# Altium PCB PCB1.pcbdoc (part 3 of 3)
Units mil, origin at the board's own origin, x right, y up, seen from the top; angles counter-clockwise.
Board outline 3256.12 x 1802.31 mil, 4 copper layers (Top Layer, Inner1, Inner2, Bottom Layer); 101 components, 70 nets, 295 pads, 151 vias.
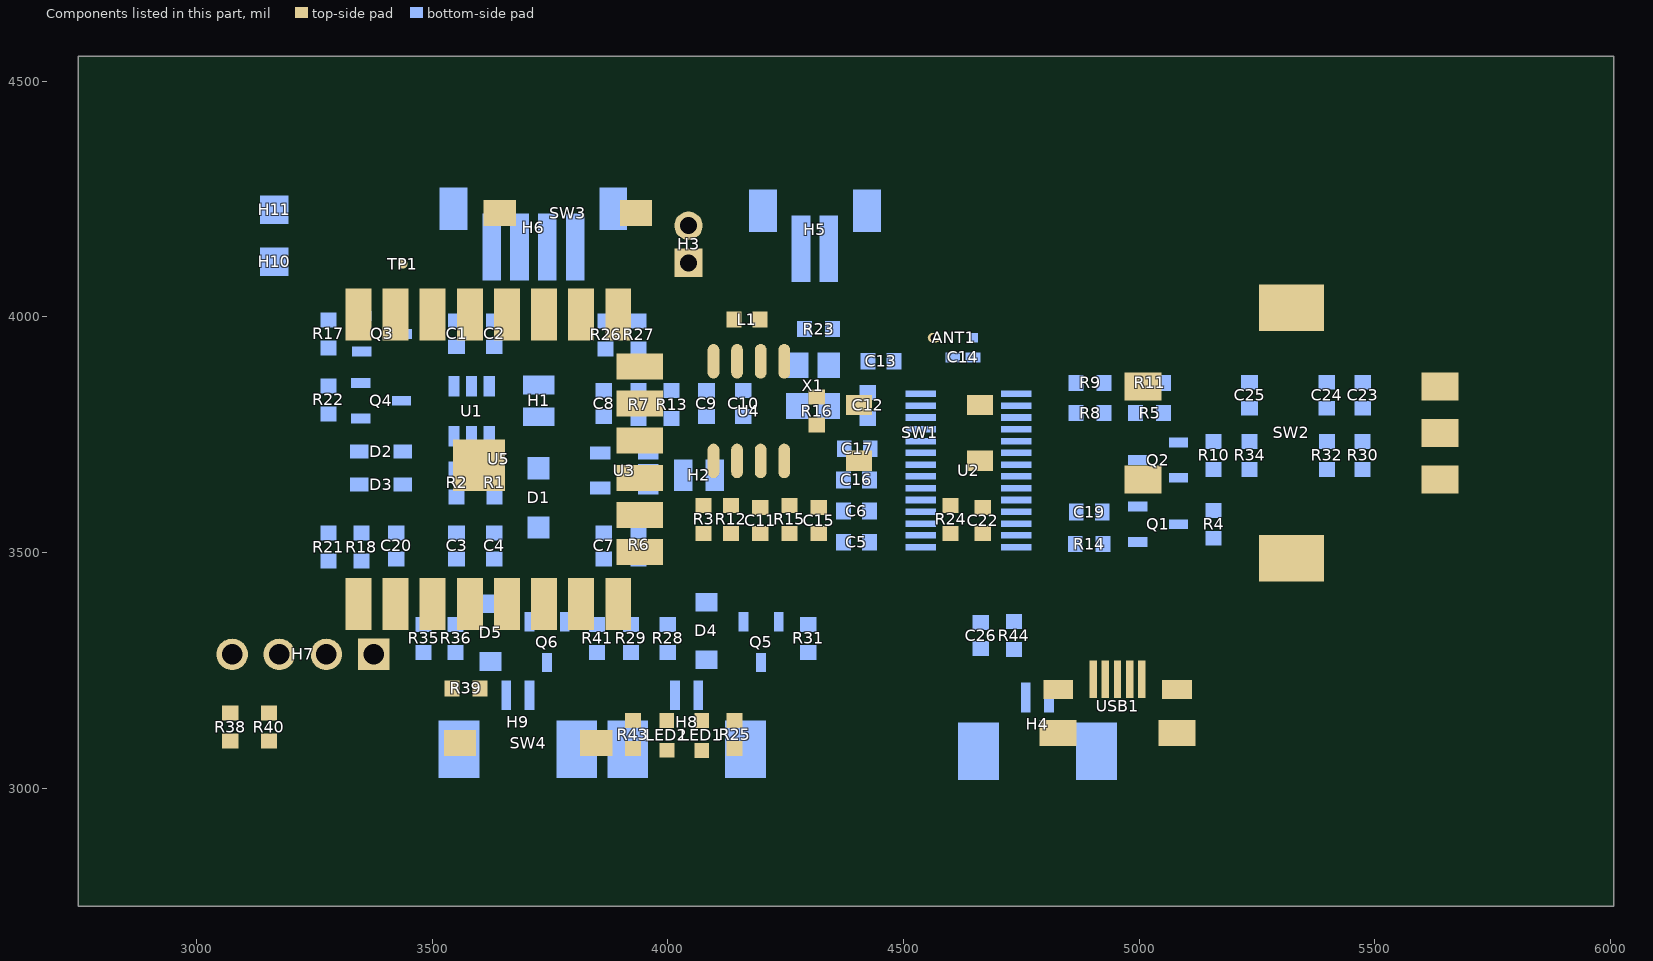
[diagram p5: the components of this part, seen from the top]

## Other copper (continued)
Bottom Layer:
  region net B+: 3260.01,4092 3372.01,4092 3372.01,3974 3260.01,3974
  region net $1N4815: 4638.01,3954 4658.01,3954 4658.01,3910 4638.01,3910
  region net VIN: 3414.01,3976 3414.01,3918 3456.01,3876 3520.01,3876 3530.01,3866 3530.01,3828 3534.01,3824 3594.01,3824 3598.01,3828 3598.01,3914 3604.01,3920 3653.92,3920 3659.96,3926.04 3659.96,3948.05 3654.01,3954 3464.01,3954 3460.01,3958 3460.01,3976 3458.01,3978 3416.01,3978
  region net VIN: 3598.01,3886 3610.01,3898 3678.01,3898 3690.01,3886 3690.01,3836 3692.01,3834 3758.01,3834 3762.01,3838 3762.01,3946 3754.01,3954 3596.01,3954 3596.01,3888
  region net $1N1680: 3608.01,3724 3608.01,3782 3616.01,3790 3668.01,3790 3690.01,3812 3760.01,3812 3764.01,3808 3764.01,3652 3760.01,3648 3678.01,3648 3674.01,3652 3674.01,3710 3660.01,3724
  region net +5V: 3528.09,3462.42 3528.09,3500.09 3534.01,3506 3696.01,3506 3700.01,3510 3700.01,3592 3696.01,3596 3614.01,3596 3610.01,3600 3610.01,3634 3614.01,3638 3820.82,3638 3835.31,3652.49 3879.51,3652.49 3884.01,3648 3884.01,3590 3882.01,3588 3820.01,3588 3814.01,3582 3814.01,3470 3806.01,3462 3528.51,3462
  region net VCC: 4079.8,3624.21 4080.01,3624 4079.8,3624
  region net VCC: 4082.01,3624 4080.01,3624 4082.01,3622
  region net VCC: 4062.01,3804 4062.01,3749.97 4074.01,3737.97 4074.01,3594 4080.01,3588 4190.01,3588 4196.01,3594 4196.01,3802 4190.01,3808 4066.01,3808
  region net $1N2005: 3936.01,3650 3938.01,3652 4008.01,3652 4012.01,3656 4012.01,3726 4014.01,3728 4052.01,3728 4054.01,3726 4054.01,3594 4048.01,3588 3944.01,3588 3936.01,3596
  region net VDDIO: 4569.44,3668.35 4449.66,3668.35 4444.01,3674 4412.01,3674 4410.01,3672 4410.01,3638 4414.14,3633.87 4442.53,3633.87 4460.01,3654 4570.01,3654.4 4570.01,3667.78
  region net +5V: 4412.01,3606 4412.01,3504 4444.01,3504 4444.01,3606
  region net VCC: 4196,3593.97 4196,3444 4190.01,3438 4070.01,3438 4064.01,3444 4064.01,3586 4074.01,3596 4195.57,3596 4196.01,3595.56 4196.01,3593.98
  region net +5V: 3803.9,3462 3803.9,3504 4040.01,3504 4044.01,3500 4044.01,3472 4034.01,3462
  region net VCC: 3896.72,3848.56 3896.72,3838.56 ccw(c3896.72,3819.81) 3881.72,3831.06 3881.72,3856.06 ccw(c3896.72,3867.31)
  region net $1N2017: 3869.01,3757.69 3859.01,3757.69 ccw(c3840.26,3757.69) 3851.51,3772.69 3876.51,3772.69 ccw(c3887.76,3757.69)
  region net $1N2017: 3896.72,3793.44 3896.72,3783.44 ccw(c3896.72,3764.69) 3881.72,3775.94 3881.72,3800.94 ccw(c3896.72,3812.19)
  region net VCC: 4059.04,3799.9 4063.58,3809.5 ccw(c4079.49,3830.71) 4079.49,3804.19 4064.34,3783.99 ccw(c4037.83,3783.99)
  region net +5V: 3557.51,3448.19 3542.51,3448.19 ccw(c3507.59,3448.19) 3534.29,3470.69 3568.76,3470.69 ccw(c3585.63,3448.19)
  region net +5V: 4435.5,3481.79 4420.5,3481.79 ccw(c4387.01,3481.79) 4411.81,3504.29 4443.31,3504.29 ccw(c4471.81,3481.79)
  region net +5V: 4444.01,3594 4444.01,3582 ccw(c4502.14,3573) 4443.31,3573 4443.31,3603 ccw(c4502.17,3603)
  region net $1N2789: 4394.29,3850 4394.29,3858 ccw(c4406.29,3883.4) 4406.29,3855.31 4406.29,3844 ccw(c4394.29,3835)
  region net $1N2789: 4454.45,3844.56 4454.45,3834.56 ccw(c4454.45,3820.02) 4441.72,3827.06 4441.72,3852.06 ccw(c4454.45,3859.1)
  region net $1N2785: 4444.44,3891.67 4440.75,3884.04 ccw(c4428.02,3867.07) 4428.02,3888.28 4440.19,3904.39 ccw(c4461.41,3904.39)
  region net $1N2785: 4396.7,3902 4396.7,3910 ccw(c4396.7,3925) 4408.7,3916 4408.7,3896 ccw(c4396.7,3887)
  region net $1N2965: 4450.62,3706.02 4445.51,3696.98 ccw(c4429.6,3675.77) 4429.6,3702.28 4445.31,3721.93 ccw(c4471.83,3721.93)
  region net $1N4810: 4613.51,3880.87 4598.51,3880.87 ccw(c4567.14,3880.87) 4588.99,3903.37 4620.1,3903.37 ccw(c4655.2,3880.87)
  region net DACL: 4946.01,3591 4946.01,3581 ccw(c4946.01,3572.21) 4937.31,3573.5 4937.31,3598.5 ccw(c4946.01,3599.79)
  region net PA0: 4845.39,3599.98 4850.5,3609.02 ccw(c4866.41,3630.23) 4866.41,3603.72 4850.7,3584.07 ccw(c4824.18,3584.07)
  region net EC11_A: 5478.95,3775.5 5468.95,3775.5 ccw(c5450.2,3775.5) 5461.45,3790.5 5486.45,3790.5 ccw(c5497.7,3775.5)
  region net EC11_B: 5403.06,3775.5 5393.06,3775.5 ccw(c5374.31,3775.5) 5385.56,3790.5 5410.56,3790.5 ccw(c5421.81,3775.5)
  region net EC11_D: 5239.06,3775.5 5229.06,3775.5 ccw(c5210.31,3775.5) 5221.56,3790.5 5246.56,3790.5 ccw(c5257.81,3775.5)
  region net POWER_ADC: 3433.51,3458 3418.51,3458 ccw(c3405.72,3458) 3407.26,3470.69 3441.72,3470.69 ccw(c3447.42,3458)
  region net POWER_ADC: 3383.79,3478.5 3383.79,3493.5 ccw(c3383.79,3526.98) 3406.29,3502.19 3406.29,3470.69 ccw(c3383.79,3442.18)
  region net $1N5780: 4751.98,3246.64 4766.98,3246.64 ccw(c4860.87,3246.64) 4769.72,3224.14 4749.25,3224.14 ccw(c4658.1,3246.64)
  region net SGND: 4838.92,3233.47 4830.78,3204.11 ccw(c4863.9,3170.99) 4818.94,3184.13 4818.94,3221.63 ccw(c4805.8,3266.59)
  region net $1N8684: 4097.35,3204.59 4097.35,3189.59 ccw(c4097.35,3161.46) 4074.85,3178.34 4074.85,3215.84 ccw(c4097.35,3232.71)
  region net $1N8688: 4007.9,3251.08 4022.9,3251.08 ccw(c4116.78,3251.08) 4025.63,3228.58 4005.16,3228.58 ccw(c3914.01,3251.08)
  region net $1N9109: 3699.12,3229.25 3714.12,3229.25 ccw(c3716.85,3234.51) 3716.85,3228.58 3696.38,3228.58 ccw(c3696.38,3234.51)
  region net $1N9106: 3649.9,3235.59 3664.9,3235.59 ccw(c3675.24,3235.59) 3667.63,3228.58 3647.16,3228.58 ccw(c3639.55,3235.59)
  region net $1N10424: 3430.37,3743.76 3440.37,3743.76 ccw(c3459.12,3743.76) 3447.87,3728.76 3422.87,3728.76 ccw(c3411.62,3743.76)
  region net EC11_D: 3353.34,3676.74 3338.34,3676.74 ccw(c3310.22,3676.74) 3327.09,3699.24 3364.59,3699.24 ccw(c3381.47,3676.74)
  region net EC11_D: 3378.11,3721.5 3378.11,3706.5 ccw(c3378.11,3691.97) 3365.53,3699.24 3365.53,3728.76 ccw(c3378.11,3736.03)
  region net POWER_SW: 3445.67,3610.16 3430.67,3610.16 ccw(c3408.88,3610.16) 3419.42,3629.24 3456.92,3629.24 ccw(c3467.46,3610.16)
  region net EC11_D: 3338.34,3681.26 3353.34,3681.26 ccw(c3381.47,3681.26) 3364.59,3658.76 3327.09,3658.76 ccw(c3310.22,3681.26)
  region net $1N9109: 3655.58,3370.05 3641.04,3363.38 ccw(c3617.17,3331.56) 3617.17,3371.34 3647.63,3393.91 ccw(c3687.4,3393.91)
  region net $1N9106: 3577.88,3280.84 3577.88,3295.84 ccw(c3600.38,3327.53) 3600.38,3288.66 3600.38,3269.59 ccw(c3577.88,3252.72)
  region net $1N9106: 3655.58,3248.01 3641.04,3241.34 ccw(c3617.17,3209.52) 3617.17,3249.3 3647.63,3271.87 ccw(c3687.4,3271.87)
  region net $1N8684: 4083.51,3364 4068.51,3364 ccw(c4057.1,3364) 4058.38,3375.34 4094.76,3375.34 ccw(c4094.84,3364)
  region net $1N8688: 4035.88,3280.84 4035.88,3295.84 ccw(c4058.38,3373.98) 4058.38,3292.66 4058.38,3269.59 ccw(c4035.88,3252.72)
  region net $1N2005: 4008.64,3633.02 4004.96,3643.49 ccw(c3982.89,3665.57) 4012.86,3656.82 4012.86,3631.82 ccw(c4010.41,3631.25)
  region net VCC: 3406.82,3325.42 3417.43,3314.81 ccw(c3449.24,3290.95) 3409.47,3290.95 3382.95,3317.46 ccw(c3382.95,3357.24)
  region net $1N5279: 5007.94,3540.96 5026.24,3545.12 ccw(c5066.03,3505.33) 5017.07,3533.07 4994.62,3533.07 ccw(c4985.86,3563.04)
  region net PA2: 4967.06,3619.92 4985.35,3615.76 ccw(c5007.43,3637.84) 4998.67,3607.87 4976.22,3607.87 ccw(c4927.27,3580.13)
  region net TXD: 5097.05,3575.78 5109.09,3573.68 ccw(c5130.3,3557.77) 5103.79,3557.77 5081.14,3570.47 ccw(c5081.14,3596.99)
  region net $1N5314: 5047.94,3727 5047.94,3737 ccw(c5047.94,3756.81) 5062.94,3743.87 5062.94,3722.93 ccw(c5047.94,3697.34)
  region net RXD: 5078.37,3684 5088.37,3684 ccw(c5106.97,3684) 5095.87,3669.07 5070.87,3669.07 ccw(c5059.76,3684)
  region net PA3: 4991.65,3721.47 5001.65,3721.47 ccw(c5020.4,3721.47) 5009.15,3706.47 4984.15,3706.47 ccw(c4972.9,3721.47)
  region net PA3: 4961.22,3681.5 4961.22,3691.5 ccw(c4961.22,3710.25) 4976.22,3699 4976.22,3685.53 ccw(c4976.22,3655.58)
  region net $1N8729: 4179.03,3345.54 4178.38,3324.98 ccw(c4154.51,3293.16) 4154.51,3332.94 4171.08,3369.4 ccw(c4210.85,3369.4)
  region net $1N8684: 4180.23,3238.26 4179.58,3258.82 ccw(c4147.76,3282.68) 4187.53,3282.68 4204.1,3246.22 ccw(c4204.1,3206.44)
  region net $1N9116: 3699.11,3382.6 3714.11,3382.6 ccw(c3728.67,3382.6) 3717.08,3373.78 3696.13,3373.78 ccw(c3684.54,3382.6)
  region net $1N9109: 3726.23,3238.26 3725.58,3258.82 ccw(c3693.76,3282.68) 3733.53,3282.68 3750.1,3246.22 ccw(c3750.1,3206.44)
  region net $1N9109: 3711.03,3259.14 3711.03,3274.14 ccw(c3711.03,3302.26) 3733.53,3285.39 3733.53,3247.89 ccw(c3711.03,3231.01)
  region net $1N10424: 3376.83,3921.62 3373.49,3910.82 ccw(c3357.58,3889.61) 3357.58,3916.13 3371.07,3937.07 ccw(c3394.65,3937.07)
  region net $1N10424: 3315.22,3921.6 3315.22,3931.6 ccw(c3315.22,3954.89) 3330.22,3937.07 3330.22,3916.13 ccw(c3315.22,3898.31)
  region net $1N10478: 3319.27,3807.33 3337.77,3802.96 ccw(c3359.85,3825.04) 3351.09,3795.07 3328.22,3795.07 ccw(c3284.34,3772.41)
  region net $1N10424: 3427.01,3847.47 3437.01,3847.47 ccw(c3455.76,3847.47) 3444.51,3832.47 3419.51,3832.47 ccw(c3408.26,3847.47)
  region net $1N10424: 3440.37,3796.53 3430.37,3796.53 ccw(c3411.62,3796.53) 3422.87,3811.53 3447.87,3811.53 ccw(c3459.12,3796.53)
  region net $1N1955: 3915.7,3555.24 3918.05,3567.03 ccw(c3933.96,3588.24) 3933.96,3561.73 3921,3539.33 ccw(c3894.48,3539.33)
  region net +5V: 3929.51,3448.15 3914.51,3448.15 ccw(c3878.77,3470.65) 3921,3470.65 3940.76,3470.65 ccw(c3957.63,3448.15)
  region net VCC: 3906,3838.56 3906,3848.56 ccw(c3906,3867.31) 3921,3856.06 3921,3831.06 ccw(c3906,3819.81)
  region net VCC: 3955.58,3864.65 3960.32,3855.24 ccw(c3981.53,3839.33) 3955.01,3839.33 3939.67,3859.35 ccw(c3939.67,3885.86)
  region net $1N2017: 3906,3783.44 3906,3793.44 ccw(c3906,3813.82) 3921,3800.03 3921,3775.94 ccw(c3906,3764.69)
  region net $1N2017: 3966.89,3809.37 3962.91,3791.25 ccw(c3984.99,3769.17) 3955.01,3777.93 3955.01,3800.03 ccw(c3921.76,3854.5)
  region net $1N2017: 3993.95,3822.29 3985.75,3828.23 ccw(c3964.53,3844.14) 3991.05,3844.14 4009.86,3827.59 ccw(c4009.86,3801.08)
  region net $1N1696: 3541.61,3708.54 3551.61,3708.54 ccw(c3570.36,3708.54) 3559.11,3693.54 3535,3693.54 ccw(c3521.28,3708.54)
  region net $1N1696: 3584.01,3682.66 3584.01,3672.66 ccw(c3584.01,3653.91) 3569.01,3665.16 3569.01,3690.16 ccw(c3584.01,3701.41)
  region net $1N1696: 3600,3672.66 3600,3682.66 ccw(c3600,3701.41) 3615,3690.16 3615,3665.16 ccw(c3600,3653.91)
  region net USB_DP: 4871.35,3770.34 4861.35,3770.34 ccw(c4852.61,3770.34) 4853.85,3778.99 4878.85,3778.99 ccw(c4880.09,3770.34)
  region net USB_DM: 4851.11,3837.69 4845.17,3845.89 ccw(c4823.95,3861.8) 4850.47,3861.8 4867.02,3842.99 ccw(c4867.02,3816.48)
  region net $1N5279: 5144.24,3655.16 5135.69,3660.76 ccw(c5114.48,3676.67) 5141,3676.67 5160.15,3660.46 ccw(c5160.15,3633.95)
  region net VDDIO: 5135.69,3750.9 5143.9,3756.84 ccw(c5159.81,3778.05) 5159.81,3751.54 5141,3734.99 ccw(c5114.48,3734.99)
  region net $1N5314: 5013.52,3845.89 5007.59,3837.69 ccw(c4991.68,3816.48) 4991.68,3842.99 5008.22,3861.8 ccw(c5034.74,3861.8)
  region net VDDIO: 5027.84,3873.22 5037.31,3884.96 ccw(c5061.17,3916.78) 5061.17,3877.01 5035.79,3849.36 ccw(c4996.02,3849.36)
  region net VDDIO: 5056.67,3827.99 5046.67,3827.99 ccw(c5027.92,3827.99) 5039.17,3842.99 5064.17,3842.99 ccw(c5075.42,3827.99)
  region net TXD: 5126,3584.66 5126,3594.66 ccw(c5126,3613.41) 5141,3602.16 5141,3577.16 ccw(c5126,3565.91)
  region net +5V: 5184.2,3547.27 5180.88,3529.81 ccw(c5198,3514.46) 5175.01,3514.46 5175.01,3546.22 ccw(c5178.95,3552.53)
  region net PA3: 5001.65,3763.99 4991.65,3763.99 ccw(c4972.9,3763.99) 4984.15,3778.99 5008.22,3778.99 ccw(c5022.04,3763.99)
  region net VDDIO: 5082.54,3801 5082.54,3791 ccw(c5082.54,3772.25) 5067.54,3783.5 5067.54,3808.5 ccw(c5082.54,3819.75)
  region net VDDIO: 5046.67,3828.01 5056.67,3828.01 ccw(c5075.42,3828.01) 5064.17,3813.01 5039.17,3813.01 ccw(c5027.92,3828.01)
  region net SGND: 4871.85,3478.49 4856.85,3478.49 ccw(c4822.44,3478.49) 4848.47,3500.99 4880.22,3500.99 ccw(c4906.26,3478.49)
  region net SGND: 4841.58,3531.58 4850.44,3541.1 ccw(c4870.32,3570.5) 4870.32,3535.01 4848.47,3510.89 ccw(c4814,3510.89)
  region net +5V: 4267.04,3986.7 4277.65,3997.3 ccw(c4299.85,4033.32) 4299.85,3991.01 4274.47,3963.36 ccw(c4234.09,3963.36)
  region net MUSIC_SW: 4381.96,3981.5 4381.96,3966.5 ccw(c4381.96,3947.56) 4365.54,3956.99 4365.54,3991.01 ccw(c4381.96,4000.44)
  region net MUSIC_SW: 4342.17,4000.34 4357.17,4000.34 ccw(c4366.55,4000.34) 4365.54,3991.01 4333.79,3991.01 ccw(c4332.78,4000.34)
  region net VCC: 3992.51,3384 4007.51,3384 ccw(c4034.28,3384) 4017.01,3363.54 3983,3363.54 ccw(c3965.73,3384)
  region net $1N8688: 4022.9,3249.96 4007.9,3249.96 ccw(c3979.77,3249.96) 3996.65,3272.46 4017.01,3272.46 ccw(c4062.99,3272.46)
  region net $1N8688: 4039.51,3295.84 4039.51,3280.84 ccw(c4039.51,3246.43) 4017.01,3272.46 4017.01,3304.22 ccw(c4039.51,3330.25)
  region net $1N8688: 3960.5,3280.84 3960.5,3295.84 ccw(c3960.5,3330.25) 3983,3304.22 3983,3272.46 ccw(c3960.5,3246.43)
  region net +5V: 3914.51,3386.04 3929.51,3386.04 ccw(c3960.88,3386.04) 3939.01,3363.54 3905,3363.54 ccw(c3883.13,3386.04)
  region net $1N8688: 3961.51,3295.84 3961.51,3280.84 ccw(c3961.51,3246.43) 3939.01,3272.46 3939.01,3304.22 ccw(c3961.51,3330.25)
  region net $1N8729: 4273.04,3302.7 4284.78,3312.17 ccw(c4308.65,3343.99) 4308.65,3304.22 4281,3278.83 ccw(c4241.22,3278.83)
  region net LED_PWM: 4330.01,3352.66 4330.01,3342.66 ccw(c4330.01,3323.91) 4315.01,3335.16 4315.01,3360.16 ccw(c4330.01,3371.41)
  region net VCC: 3442.5,3340.16 3442.5,3355.16 ccw(c3442.5,3389.57) 3465,3363.54 3465,3331.78 ccw(c3442.5,3305.75)
  region net $1N9106: 3521.51,3295.84 3521.51,3280.84 ccw(c3521.51,3246.43) 3499.01,3272.46 3499.01,3304.22 ccw(c3521.51,3330.25)
  region net +5V: 3542.51,3386.04 3557.51,3386.04 ccw(c3588.88,3386.04) 3567.01,3363.54 3533,3363.54 ccw(c3511.13,3386.04)
  region net $1N9106: 3589.51,3295.84 3589.51,3280.84 ccw(c3589.51,3246.43) 3567.01,3272.46 3567.01,3304.22 ccw(c3589.51,3330.25)
  region net $1N9106: 3510.5,3280.84 3510.5,3295.84 ccw(c3510.5,3330.25) 3533,3304.22 3533,3272.46 ccw(c3510.5,3246.43)
  region net $1N9116: 3842.51,3370 3857.51,3370 ccw(c3867.01,3373.76) 3867.01,3363.54 3833,3363.54 ccw(c3833,3373.76)
  region net MOTOR_PWM: 3857.51,3260 3842.51,3260 ccw(c3829.58,3260) 3833,3272.46 3867.01,3272.46 ccw(c3870.43,3260)
  region net +5V: 5442,3671.34 5442,3681.34 ccw(c5442,3700.09) 5457,3688.84 5457,3663.84 ccw(c5442,3652.59)
  region net EC11_A: 5468.95,3766.54 5478.95,3766.54 ccw(c5497.7,3766.54) 5486.45,3751.54 5461.45,3751.54 ccw(c5450.2,3766.54)
  region net +5V: 5380.24,3655.16 5375.69,3664.76 ccw(c5354.48,3680.67) 5381,3680.67 5396.15,3660.46 ccw(c5396.15,3633.95)
  region net +5V: 5430.01,3681.34 5430.01,3671.34 ccw(c5430.01,3652.59) 5415.01,3663.84 5415.01,3688.84 ccw(c5430.01,3700.09)
  region net EC11_B: 5393.06,3766.54 5403.06,3766.54 ccw(c5421.81,3766.54) 5410.56,3751.54 5385.56,3751.54 ccw(c5374.31,3766.54)
  region net +5V: 5239.01,3645.46 5229.01,3645.46 ccw(c5210.26,3645.46) 5221.51,3660.46 5246.51,3660.46 ccw(c5257.76,3645.46)
  region net EC11_D: 5219.9,3714.48 5211.69,3720.42 ccw(c5190.48,3736.33) 5217,3736.33 5235.81,3719.78 ccw(c5235.81,3693.27)
  region net EC11_D: 5229.06,3766.54 5239.06,3766.54 ccw(c5257.81,3766.54) 5246.56,3751.54 5221.56,3751.54 ccw(c5210.31,3766.54)
  region net $1N10424: 3312.01,3931.6 3312.01,3921.6 ccw(c3312.01,3884.15) 3297.01,3918.46 3297.01,3939.1 ccw(c3312.01,3950.35)
  region net POWER_IO: 3304.97,3779.98 3293.23,3770.51 ccw(c3269.36,3738.69) 3269.36,3778.46 3297.01,3803.85 ccw(c3336.79,3803.85)
  region net $1N10478: 3302.32,3838.42 3294.11,3832.48 ccw(c3278.2,3811.27) 3278.2,3837.78 3297.01,3854.33 ccw(c3323.53,3854.33)
  region net VIN: 3356.17,3565.23 3375.32,3570.25 ccw(c3400.95,3544.62) 3367.01,3557.34 3342.85,3557.34 ccw(c3334.09,3587.31)
  region net POWER_ADC: 3310.5,3474.65 3310.5,3489.65 ccw(c3310.5,3524.06) 3333,3498.02 3333,3466.27 ccw(c3310.5,3440.24)
  region net POWER_ADC: 3389.51,3493.5 3389.51,3478.5 ccw(c3389.51,3450.38) 3367.01,3467.25 3367.01,3498.02 ccw(c3389.51,3551.74)
  region net POWER_ADC: 3319.51,3489.65 3319.51,3474.65 ccw(c3319.51,3440.24) 3297.01,3466.27 3297.01,3498.02 ccw(c3319.51,3524.06)
  region net POWER_LED: 3854.73,3908.32 3842.99,3917.79 ccw(c3811.17,3941.65) 3850.95,3941.65 3878.6,3916.27 ccw(c3878.6,3876.5)
  region net $1N10993: 3844.01,3985 3844.01,3995 ccw(c3843.42,4002.5) 3850.95,4002.5 3850.95,3977.5 ccw(c3843.42,3977.5)
  region net SPK_LED: 3924.78,3908.32 3913.04,3917.79 ccw(c3881.22,3941.65) 3921,3941.65 3948.65,3916.27 ccw(c3948.65,3876.5)
  region net $1N10998: 3933.01,4013.96 3943.01,4013.96 ccw(c3950.51,4014.9) 3950.51,4007.34 3925.51,4007.34 ccw(c3925.51,4014.9)
  region net $1N1696: 3551.61,3710.2 3541.61,3710.2 ccw(c3521.68,3710.2) 3534.79,3725.2 3558.42,3725.2 ccw(c3571.53,3710.2)
  region net VIN: 3522.8,3822.28 3526.9,3840.52 ccw(c3504.82,3862.6) 3534.79,3853.84 3534.79,3831.5 ccw(c3564.09,3780.99)
  region net $1N2017: 3859.01,3740.14 3869.01,3740.14 ccw(c3887.76,3740.14) 3876.51,3725.14 3851.51,3725.14 ccw(c3840.26,3740.14)
  region net $1N2005: 3995.6,3641.56 3995.6,3631.56 ccw(c3995.6,3612.81) 3980.6,3624.06 3980.6,3649.06 ccw(c3995.6,3660.31)
  region net $1N1955: 3927.45,3706.44 3927.45,3716.44 ccw(c3927.45,3726.66) 3937.3,3723.94 3937.3,3698.94 ccw(c3927.45,3696.22)
  region net DACR: 4541.05,3492.97 4531.05,3492.97 ccw(c4518.43,3492.97) 4523.55,3504.5 4548.55,3504.5 ccw(c4553.66,3492.97)
  region net MOTOR_PWM: 4504.51,3531.5 4504.51,3541.5 ccw(c4449.73,3543.5) 4504.54,3543.5 4504.54,3529.5 ccw(c4449.73,3529.5)
  region net LED_PWM: 4491.51,3556.5 4491.51,3566.5 ccw(c4491.51,3609.99) 4504.54,3568.5 4504.54,3554.5 ccw(c4491.51,3513.01)
  region net +5V: 4492.19,3630.19 4492.19,3642.19 ccw(c4492.19,3701.02) 4504.54,3643.5 4504.54,3629.5 ccw(c4492.19,3519.15)
  region net $1N2965: 4489.54,3681.5 4489.54,3691.5 ccw(c4489.54,3748.75) 4504.54,3693.5 4504.54,3679.5 ccw(c4489.54,3624.25)
  region net $1N2789: 4489.54,3806.5 4489.54,3816.5 ccw(c4489.54,3873.75) 4504.54,3818.5 4504.54,3804.5 ccw(c4489.54,3749.25)
  region net $1N2785: 4493.95,3832.5 4493.95,3840.5 ccw(c4493.95,3860.71) 4504.54,3843.5 4504.54,3829.5 ccw(c4493.95,3812.29)
  region net KEY_IO: 4691.9,3831.5 4691.9,3841.5 ccw(c4691.9,3898.75) 4706.9,3843.5 4706.9,3829.5 ccw(c4691.9,3774.25)
  region net EC11_B: 4784.46,3816.5 4784.46,3806.5 ccw(c4784.46,3763.33) 4771.47,3804.5 4771.47,3818.5 ccw(c4784.46,3859.67)
  region net EC11_A: 4786.47,3793.57 4786.47,3783.57 ccw(c4786.47,3753.93) 4771.47,3779.5 4771.47,3793.5 ccw(c4771.47,5295.51)
  region net USB_DM: 4786.47,3766.5 4786.47,3756.5 ccw(c4786.47,3699.25) 4771.47,3754.5 4771.47,3768.5 ccw(c4786.47,3823.75)
  region net USB_DP: 4786.47,3741.5 4786.47,3731.5 ccw(c4786.47,3674.25) 4771.47,3729.5 4771.47,3743.5 ccw(c4786.47,3798.75)
  region net PA3: 4786.47,3691.5 4786.47,3681.5 ccw(c4786.47,3624.25) 4771.47,3679.5 4771.47,3693.5 ccw(c4786.47,3748.75)
  region net PA2: 4786.47,3666.5 4786.47,3656.5 ccw(c4786.47,3599.25) 4771.47,3654.5 4771.47,3668.5 ccw(c4786.47,3723.75)
  region net PA1: 4691.9,3631.5 4691.9,3641.5 ccw(c4691.9,3698.75) 4706.9,3643.5 4706.9,3629.5 ccw(c4691.9,3574.25)
  region net PA0: 4786.47,3616.5 4786.47,3606.5 ccw(c4786.47,3549.25) 4771.47,3604.5 4771.47,3618.5 ccw(c4786.47,3673.75)
  region net PC7: 4698.51,3581.5 4698.51,3591.5 ccw(c4698.51,3610.13) 4706.9,3593.5 4706.9,3579.5 ccw(c4698.51,3562.87)
  region net SGND: 4790.97,3543 4790.97,3530 ccw(c4790.97,3149.5) 4771.47,3529.5 4771.47,3543.5 ccw(c4790.97,3923.5)
  region net DACL: 4786.47,3516.5 4786.47,3506.5 ccw(c4786.47,3449.25) 4771.47,3504.5 4771.47,3518.5 ccw(c4786.47,3573.75)
  region net SPK+: 4054.01,4054.63 4034.01,4054.63 ccw(c3996.51,4054.63) 4019.01,4084.63 4069.01,4084.63 ccw(c4091.51,4054.63)
  region net B+: 3564.19,4057.86 3575.17,4125.4 ccw(c3486.85,4213.72) 3606.74,4178.69 3606.74,4078.69 ccw(c3615.86,4006.19)
  region net $1N10993: 3774.5,4066.58 3757.32,4069.61 ccw(c3735.24,4047.54) 3744,4077.51 3764.22,4077.51 ccw(c3948.69,4240.77)
  region net $1N10998: 3831.17,4127.87 3836.6,4108.3 ccw(c3814.52,4086.22) 3823.28,4116.19 3823.28,4141.19 ccw(c3853.25,4149.95)
  region net $1N2789: 4294.69,3842.49 4302.41,3838.9 ccw(c4319.38,3826.17) 4298.16,3826.17 4281.96,3838.25 ccw(c4281.96,3859.46)
  region net $1N2785: 4377.09,3910 4377.09,3902 ccw(c4377.09,3887) 4365.09,3896 4365.09,3916 ccw(c4377.09,3925)
  region net PA1: 4659.01,3382.31 4669.01,3382.31 ccw(c4687.76,3382.31) 4676.51,3367.31 4651.51,3367.31 ccw(c4640.26,3382.31)
  region net $1N5780: 4704.22,3301.84 4704.22,3286.84 ccw(c4704.22,3242.59) 4681.72,3280.69 4681.72,3312.19 ccw(c4704.22,3331.48)
  region net $1N5780: 4694.5,3286.84 4694.5,3301.84 ccw(c4694.5,3336.25) 4717,3310.22 4717,3278.46 ccw(c4694.5,3252.43)
  region net $1N5780: 4758.97,3279.98 4747.23,3270.51 ccw(c4723.36,3238.69) 4723.36,3278.46 4751.01,3303.85 ccw(c4790.79,3303.85)
  region net PC7: 4711.69,3368.9 4719.9,3374.84 ccw(c4735.81,3396.05) 4735.81,3369.54 4717,3352.99 ccw(c4690.48,3352.99)
  region net B+: 3249.01,4125 3249.01,4085 ccw(c3195.01,3357) 3195.01,4087 3195.01,4147 ccw(c3249.01,4202.27)
  region net MUSIC_SW: 4365.62,3966.5 4365.62,3981.5 4367.99,3981.42 4370.13,3981.42 4371.14,3981.56 4372.12,3981.84 4373.08,3982.31 4374.02,3983.01 4374.02,3964.99 4373.08,3965.69 4372.12,3966.16 4371.14,3966.44 4370.13,3966.58 4367.99,3966.58
  region net MOTOR_PWM: 3842.51,3276.35 3857.51,3276.35 3857.43,3273.97 3857.43,3271.83 3857.56,3270.82 3857.84,3269.84 3858.31,3268.89 3859.01,3267.94 3841,3267.94 3841.7,3268.89 3842.17,3269.84 3842.45,3270.82 3842.58,3271.83 3842.58,3273.97
  region net MOTOR_PWM: 4480.03,3391.1 4487.1,3384.02 4486.36,3383.16 4485.74,3382.17 4484.81,3379.97 4484.26,3377.59 4483.99,3375.25 4471.25,3387.98 4473.6,3388.25 4475.97,3388.81 4478.18,3389.73 4479.16,3390.35
  region net +5V: 4420.5,3486.32 4435.5,3486.32 4435.42,3483.95 4435.42,3481.81 4435.55,3480.8 4435.83,3479.82 4436.3,3478.86 4437,3477.92 4418.99,3477.92 4419.69,3478.86 4420.16,3479.82 4420.44,3480.8 4420.58,3481.81 4420.57,3483.95
  region net +5V: 5229.01,3660.35 5239.01,3660.35 5239.1,3659.21 5239.35,3658.08 5240.26,3655.86 5241.54,3653.79 5243.01,3651.94 5225,3651.94 5226.47,3653.79 5227.75,3655.86 5228.66,3658.08 5228.92,3659.21
  region net +5V: 5247.54,3637.54 5240.47,3630.46 5239.67,3631.14 5238.86,3631.58 5238.04,3631.85 5237.19,3631.97 5233.25,3632.02 5245.99,3644.75 5246.03,3640.81 5246.16,3639.96 5246.42,3639.14 5246.87,3638.34
  region net DACL: 4811.82,3506.5 4811.82,3516.5 4812.96,3516.59 4814.1,3516.84 4816.31,3517.75 4818.38,3519.03 4820.23,3520.51 4820.23,3502.49 4818.38,3503.97 4816.31,3505.25 4814.1,3506.16 4812.96,3506.41
  region net DACL: 4929.66,3581 4929.66,3591 4930.8,3591.09 4931.93,3591.34 4934.14,3592.25 4936.22,3593.53 4938.06,3595.01 4938.06,3576.99 4936.22,3578.47 4934.14,3579.75 4931.93,3580.66 4930.8,3580.91
  region net MUSIC_SW: 4627.01,3719.65 4613.01,3719.65 4612.98,3721.94 4612.76,3724.14 4612.17,3726.21 4611.67,3727.16 4611,3728.06 4629.01,3728.06 4628.34,3727.16 4627.84,3726.21 4627.25,3724.14 4627.03,3721.94
  region net VDDIO: 5069.66,3791 5069.66,3801 5070.8,3801.09 5071.93,3801.34 5074.14,3802.25 5076.22,3803.53 5078.06,3805.01 5078.06,3786.99 5076.22,3788.47 5074.14,3789.75 5071.93,3790.66 5070.8,3790.91
  region net VDDIO: 5101.2,3799.54 5102.72,3783.88 5100.56,3785.95 5099.47,3786.83 5098.38,3787.5 5097.29,3787.92 5096.18,3788.02 5095.05,3787.72 5093.91,3786.96 5094.2,3804.78 5096.21,3803.13 5097.74,3802.2 5099.25,3801.24
  region net +5V: 5179.72,3528.64 5172.64,3535.71 5173.39,3536.58 5174.01,3537.56 5174.93,3539.77 5175.49,3542.14 5175.76,3544.49 5188.49,3531.75 5186.15,3531.49 5183.77,3530.93 5181.57,3530 5180.58,3529.38
  region net KEY_IO: 4657.01,3750.35 4667.01,3750.35 4667.1,3749.21 4667.35,3748.08 4668.26,3745.86 4669.54,3743.79 4671.01,3741.94 4653,3741.94 4654.47,3743.79 4655.75,3745.86 4656.66,3748.08 4656.92,3749.21
  region net USB_DM: 4775.48,3756.5 4775.48,3766.5 4776.62,3766.59 4777.75,3766.84 4779.97,3767.75 4782.04,3769.03 4783.89,3770.51 4783.89,3752.49 4782.04,3753.97 4779.97,3755.25 4777.75,3756.16 4776.62,3756.41
  region net USB_DM: 4808.18,3766.5 4808.18,3756.5 4807.04,3756.41 4805.91,3756.16 4803.69,3755.25 4801.62,3753.97 4799.77,3752.49 4799.77,3770.51 4801.62,3769.03 4803.69,3767.75 4805.91,3766.84 4807.04,3766.59
  region net USB_DP: 4816.16,3731.5 4816.16,3741.5 4817.3,3741.59 4818.43,3741.84 4820.64,3742.75 4822.72,3744.03 4824.56,3745.51 4824.56,3727.49 4822.72,3728.97 4820.64,3730.25 4818.43,3731.16 4817.3,3731.41
  region net USB_DP: 4840.53,3751.6 4847.6,3744.52 4846.86,3743.66 4846.24,3742.67 4845.31,3740.47 4844.76,3738.09 4844.49,3735.75 4831.75,3748.48 4834.1,3748.75 4836.47,3749.31 4838.68,3750.23 4839.66,3750.85
  region net TXD: 5110.32,3574.9 5103.25,3581.98 5103.99,3582.84 5104.61,3583.83 5105.54,3586.03 5106.1,3588.41 5106.36,3590.75 5119.1,3578.02 5116.75,3577.75 5114.38,3577.19 5112.17,3576.27 5111.19,3575.65
  region net TXD: 5134.95,3594.66 5134.44,3584.66 5133.3,3584.57 5132.17,3584.33 5129.97,3583.45 5127.9,3582.2 5126.03,3580.77 5126.54,3598.78 5128.36,3597.27 5130.44,3595.95 5132.67,3595.01 5133.81,3594.75
  region net RXD: 5088.37,3666.41 5078.37,3666.41 5078.28,3667.54 5078.02,3668.68 5077.11,3670.89 5075.83,3672.97 5074.36,3674.81 5092.37,3674.81 5090.9,3672.97 5089.62,3670.89 5088.71,3668.68 5088.46,3667.54
  region net EC11_B: 5393.06,3786.71 5403.06,3785.78 5403.14,3784.64 5403.38,3783.52 5404.24,3781.33 5405.45,3779.27 5406.84,3777.37 5388.85,3778.3 5390.4,3780.1 5391.74,3782.18 5392.7,3784.43 5392.96,3785.57
  region net EC11_B: 5403.06,3754.03 5393.06,3753.11 5392.96,3754.24 5392.7,3755.38 5391.74,3757.63 5390.4,3759.71 5388.85,3761.51 5406.84,3762.44 5405.45,3760.55 5404.24,3758.48 5403.38,3756.29 5403.14,3755.17
  region net EC11_A: 5468.95,3787.6 5478.95,3787.6 5479.04,3786.46 5479.3,3785.32 5480.2,3783.11 5481.49,3781.04 5482.96,3779.19 5464.95,3779.19 5466.42,3781.04 5467.7,3783.11 5468.61,3785.32 5468.86,3786.46
  region net EC11_A: 5478.95,3754.9 5468.95,3754.9 5468.86,3756.04 5468.61,3757.17 5467.7,3759.39 5466.42,3761.46 5464.95,3763.31 5482.96,3763.31 5481.49,3761.46 5480.2,3759.39 5479.3,3757.17 5479.04,3756.04
  region net EC11_A: 4790.83,3783.57 4790.83,3793.57 4791.97,3793.66 4793.11,3793.92 4795.32,3794.83 4797.39,3796.11 4799.24,3797.58 4799.24,3779.57 4797.39,3781.04 4795.32,3782.32 4793.11,3783.23 4791.97,3783.48
  region net EC11_B: 4769.12,3806.5 4768.26,3816.5 4769.4,3816.59 4770.54,3816.86 4772.78,3817.81 4774.87,3819.15 4776.67,3820.69 4777.52,3802.7 4775.64,3804.09 4773.57,3805.31 4771.38,3806.17 4770.26,3806.41
  region net EC11_D: 5213.2,3721.93 5211.72,3706.3 5209.84,3704.64 5208.4,3703.68 5206.95,3702.73 5205.05,3701.09 5204.39,3718.85 5205.54,3718.11 5206.67,3717.83 5207.78,3717.93 5208.88,3718.34 5209.97,3719.01 5211.06,3719.88
  region net EC11_D: 3364.23,3706.5 3362.16,3721.5 3364.57,3721.45 3366.78,3721.53 3367.8,3721.72 3368.78,3722.07 3369.7,3722.62 3370.56,3723.41 3372.64,3705.52 3371.6,3706.14 3370.61,3706.52 3369.64,3706.71 3368.67,3706.76 3366.62,3706.63
  region net DACR: 4531.05,3509.32 4541.05,3509.32 4541.14,3508.18 4541.39,3507.04 4542.3,3504.83 4543.58,3502.76 4545.06,3500.91 4527.04,3500.91 4528.51,3502.76 4529.8,3504.83 4530.7,3507.04 4530.96,3508.18
  region net +5V: 4125.07,3999.5 4125.07,3984.5 4122.7,3984.58 4120.55,3984.58 4119.54,3984.44 4118.57,3984.16 4117.61,3983.69 4116.66,3982.99 4116.66,4001.01 4117.61,4000.31 4118.57,3999.84 4119.54,3999.56 4120.55,3999.42 4122.7,3999.42
  region net SPK+: 4048.75,3908.73 4062.89,3922.87 4064.82,3921.06 4066.75,3919.45 4070.34,3916.84 4073.1,3915.05 4074.5,3914.1 4057.51,3897.12 4056.56,3898.51 4054.78,3901.28 4052.17,3904.86 4050.56,3906.8
  region net VCC: 4007.51,3367.65 3992.51,3367.65 3992.58,3370.03 3992.58,3372.17 3992.45,3373.18 3992.17,3374.16 3991.7,3375.11 3991,3376.06 4009.01,3376.06 4008.31,3375.11 4007.84,3374.16 4007.56,3373.18 4007.43,3372.17 4007.43,3370.03
  region net POWER_ADC: 3418.51,3474.35 3433.51,3474.35 3433.43,3471.97 3433.43,3469.83 3433.56,3468.82 3433.84,3467.84 3434.31,3466.89 3435.01,3465.94 3417,3465.94 3417.7,3466.89 3418.17,3467.84 3418.45,3468.82 3418.58,3469.83 3418.58,3471.97
  region net POWER_SW: 3430.67,3626.47 3445.67,3626.22 3445.59,3623.85 3445.58,3621.72 3445.7,3620.71 3445.97,3619.73 3446.43,3618.77 3447.12,3617.82 3429.11,3618.07 3429.82,3619 3430.3,3619.95 3430.59,3620.93 3430.73,3621.94 3430.74,3624.1
  region net POWER_LED: 3832.35,3907.5 3832.35,3892.5 3829.98,3892.58 3827.84,3892.58 3826.83,3892.44 3825.85,3892.16 3824.89,3891.69 3823.95,3890.99 3823.95,3909.01 3824.89,3908.31 3825.85,3907.84 3826.83,3907.56 3827.84,3907.42 3829.98,3907.42
  region net SPK_LED: 3792.51,3690.35 3807.51,3690.35 3807.43,3687.97 3807.43,3685.83 3807.56,3684.82 3807.84,3683.84 3808.31,3682.89 3809.01,3681.94 3791,3681.94 3791.7,3682.89 3792.17,3683.84 3792.45,3684.82 3792.58,3685.83 3792.58,3687.97
  region net B+: 3410.29,4092 cw(c3410.29,4504.41) 3263.15,4119.14 3234.86,4090.86 cw(c3059.55,3993.66) 3260.01,3993.66 3300.01,3993.66 cw(c3420.01,3899.42) 3420.01,4052
  region net MUSIC_SW: 4290.1,4067.41 4275.1,4067.41 ccw(c4263.85,4060.28) 4263.85,4073.6 4301.35,4073.6 ccw(c4301.35,4060.28)

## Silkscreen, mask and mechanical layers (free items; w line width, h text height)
Top Silkscreen Layer:
  circle w3.94: c4535.14,3753.7 r59.06
  circle w3.94: c5323.05,3753.7 r137.8
  circle w3.94: c5323.05,3753.7 r129.92
  circle w3.94: c5323.01,3753.7 r98.43
  lines w3.94: 5086.83,3635.1 5022.85,3635.1 5022.85,3674.47 5086.83,3674.47 ; 5086.83,3831.95 5022.85,3831.95 5022.85,3871.32 5086.83,3871.32 ; 5273.84,3522.89 5273.84,3457.93 5372.26,3457.93 5372.26,3522.89 ; 5273.84,3983.52 5273.84,4048.48 5372.26,4048.48 5372.26,3983.52 ; 5375.37,3859.09 ccw(c5323.05,3753.27) 5370.53,3861.36 5360.75,3856.8 5356.19,3866.57 ccw(c5323.05,3753.26) 5351.03,3867.96 5342.73,3862.15 5342.73,3644.27 5351.03,3638.46 ccw(c5323.05,3753.26) 5356.19,3639.84 5360.75,3649.62 5370.53,3645.06 ccw(c5323.05,3753.26) 5375.38,3647.32 5378.17,3657.74 5388.59,3654.95 ccw(c5323.05,3753.27) 5392.97,3658.02 5393.91,3668.76 5404.65,3667.82 ccw(c5323.05,3753.27) 5408.44,3671.6 5407.49,3682.35 5418.24,3683.29 ccw(c5323.05,3753.27) 5421.31,3687.67 5418.52,3698.09 5428.94,3700.88 ccw(c5323.05,3753.26) 5431.2,3705.73 5426.64,3715.5 5436.41,3720.06 ccw(c5323.05,3753.26) 5437.8,3725.23 5431.61,3734.07 5440.45,3740.25 ccw(c5323.05,3753.26) 5440.91,3745.58 5433.29,3753.21 5440.91,3760.84 ccw(c5323.05,3753.26) 5440.45,3766.16 5431.61,3772.35 5437.8,3781.19 ccw(c5323.05,3753.27) 5436.41,3786.35 5426.64,3790.91 5431.2,3800.69 ccw(c5323.05,3753.26) 5428.94,3805.53 5418.52,3808.33 5421.31,3818.75 ccw(c5323.05,3753.26) 5418.24,3823.13 5407.49,3824.07 5408.43,3834.81 ccw(c5323.05,3753.26) 5404.65,3838.59 5393.91,3837.65 5392.97,3848.4 ccw(c5323.05,3753.26) 5388.59,3851.47 5378.17,3848.68 5375.38,3859.09 ; 5559.27,3635.1 5635.06,3635.1 5635.06,3674.47 5559.27,3674.47 ; 5559.27,3831.95 5635.06,3831.95 5635.06,3871.32 5559.27,3871.32 ; 4417.01,3635.26 4653.23,3635.22 4653.27,3871.44 4417.05,3871.48 4417.01,3635.26 ; 5086.83,3522.89 5559.27,3522.89 5559.27,3983.52 5086.83,3983.52 5086.83,3522.89 ; 5205.19,3745.58 5212.81,3753.21 5205.19,3760.84 cw(c5323.05,3753.27) 5205.65,3766.16 5214.49,3772.35 5208.3,3781.19 cw(c5323.05,3753.26) 5209.68,3786.35 5219.46,3790.91 5214.9,3800.69 cw(c5323.05,3753.27) 5217.16,3805.53 5227.58,3808.33 5224.79,3818.75 cw(c5323.05,3753.26) 5227.86,3823.13 5238.6,3824.07 5237.66,3834.81 cw(c5323.05,3753.27) 5241.44,3838.59 5252.19,3837.65 5253.13,3848.4 cw(c5323.05,3753.26) 5257.51,3851.47 5267.93,3848.68 5270.72,3859.09 cw(c5323.05,3753.27) 5275.57,3861.36 5285.35,3856.8 5289.9,3866.57 cw(c5323.05,3753.26) 5295.07,3867.96 5303.36,3862.15 5303.36,3644.27 5295.07,3638.46 cw(c5323.05,3753.26) 5289.9,3639.84 5285.35,3649.62 5275.57,3645.06 cw(c5323.05,3753.26) 5270.72,3647.32 5267.93,3657.74 5257.51,3654.95 cw(c5323.05,3753.27) 5253.13,3658.02 5252.19,3668.76 5241.44,3667.82 cw(c5323.05,3753.27) 5237.66,3671.6 5238.6,3682.35 5227.86,3683.29 cw(c5323.05,3753.26) 5224.79,3687.67 5227.58,3698.09 5217.16,3700.88 cw(c5323.05,3753.26) 5214.9,3705.73 5219.46,3715.5 5209.68,3720.06 cw(c5323.05,3753.26) 5208.3,3725.23 5214.49,3734.07 5205.65,3740.25 cw(c5323.05,3753.27) 5205.18,3745.58
Mechanical Layer:
  circle w3.94: c3334.86,3120.7 r88.58
  circle w3.94: c3334.86,3120.7 r43.31
  circle w3.94: c3472.66,3120.7 r29.53
  circle w3.94: c5224.62,3120.7 r88.58
  circle w3.94: c5224.62,3120.7 r43.31
  circle w3.94: c5638.01,4183.7 r88.58
  circle w3.94: c5638.01,4183.7 r43.31
  circle w3.94: c5500.21,4183.7 r29.53
  circle w3.94: c3334.86,4183.7 r88.58
  circle w3.94: c3334.86,4183.7 r43.31
  circle w3.94: c3472.66,4183.7 r29.53
  region: 5136.04,3120.93 ccw(c5224.62,3120.93) 5313.21,3120.93 ccw(c5224.62,3120.93)
  region: 3246.28,3120.93 ccw(c3334.86,3120.93) 3423.44,3120.93 ccw(c3334.86,3120.93)
  region: 3378.17,3120.93 cw(c3334.86,3120.93) 3291.55,3120.93 cw(c3334.86,3120.93)
  region: 5549.43,4183.94 ccw(c5638.01,4183.94) 5726.59,4183.94 ccw(c5638.01,4183.94)
  region: 3246.28,4183.94 ccw(c3334.86,4183.94) 3423.44,4183.94 ccw(c3334.86,4183.94)
  region: 3423.44,3120.93 cw(c3334.86,3120.93) 3246.28,3120.93 cw(c3334.86,3120.93)
  region: 3246.28,4183.94 cw(c3334.86,4183.94) 3423.44,4183.94 cw(c3334.86,4183.94)
  region: 3291.55,4183.94 cw(c3334.86,4183.94) 3378.17,4183.94 cw(c3334.86,4183.94)
  region: 5313.21,3120.93 cw(c5224.62,3120.93) 5136.04,3120.93 cw(c5224.62,3120.93)
  region: 5267.93,3120.93 cw(c5224.62,3120.93) 5181.32,3120.93 cw(c5224.62,3120.93)
  lines w1: 3291.55,3120.93 ccw(c3334.86,3120.93) 3378.17,3120.93 ccw(c3334.86,3120.93) 3291.55,3120.93 ; 3291.55,4183.94 ccw(c3334.86,4183.94) 3378.17,4183.94 ccw(c3334.86,4183.94) 3291.55,4183.94 ; 3443.13,3120.93 ccw(c3472.66,3120.93) 3502.18,3120.93 ccw(c3472.66,3120.93) 3443.13,3120.93 ; 3443.13,4183.94 cw(c3472.66,4183.94) 3502.18,4183.94 cw(c3472.66,4183.94) 3443.13,4183.94 ; 5181.32,3120.93 ccw(c5224.62,3120.93) 5267.93,3120.93 ccw(c5224.62,3120.93) 5181.32,3120.93 ; 5471.13,4183.94 cw(c5500.66,4183.94) 5530.18,4183.94 cw(c5500.66,4183.94) 5471.13,4183.94 ; 5594.7,4183.94 ccw(c5638.01,4183.94) 5681.32,4183.94 ccw(c5638.01,4183.94) 5594.7,4183.94
  lines w3.94: 4041.04,4302.03 4041.04,3751.38 ccw(c4535.14,3751.38) 4535.14,3257.28 5662.96,3257.28
Mech6:
  drawing of 1074 lines, arcs and shapes, not listed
